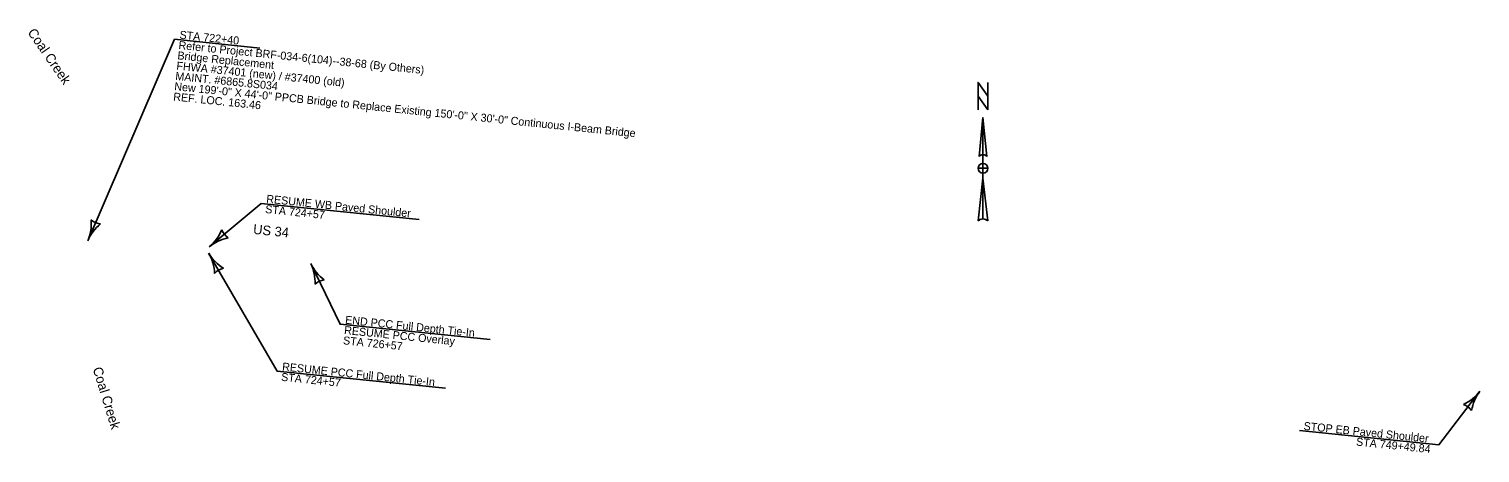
# Model space of a CAD drawing. Extents: x 22712865 to 22760106, y 6235088 to 6238602.
# Drawn here: x 22749200 to 22752029, y 6237597 to 6238424 of the extents above; entities that cross this region are included whole.
import ezdxf

# ---------------------------------------------------------------- set-up
doc = ezdxf.new("R2010")
doc.units = 0
for name, color, linetype in [('Default', 7, 'Continuous'), ('Draft_3', 7, 'Continuous'), ('dsnTextOdd', 7, 'Continuous')]:
    doc.layers.add(name, color=color, linetype=linetype)

msp = doc.modelspace()

# ---------------------------------------------------------------- linework, layer by layer
at = {"layer": 'Draft_3'}
for points in [[(22749314.9, 6238011), (22749484.1, 6238403.8), (22749650.6, 6238386.7)], [(22749551.8, 6237998.9), (22749653.1, 6238083.9), (22749960.8, 6238052.5)], [(22749550.6, 6237986.9), (22749684, 6237756.9), (22750012.5, 6237723.4)], [(22749749.6, 6237966.6), (22749806.8, 6237848.1), (22750099.4, 6237818.2)], [(22752028.8, 6237717.7), (22751948.8, 6237613.2), (22751677.3, 6237641)]]:
    msp.add_lwpolyline(points, dxfattribs=at)
for centre, radius, start, end in [((22749236.8, 6238044.6), 85, 336.7001, 4.7726), ((22749393, 6237977.4), 85, 128.6276, 156.7001), ((22749343.1, 6238076.5), 32.8, 228.9668, 264.4335), ((22749497.2, 6238064), 85, 310.0417, 338.1142), ((22749606.5, 6237933.8), 85, 101.9692, 130.0417), ((22749606.4, 6238044.7), 32.8, 202.3084, 237.7751), ((22749624.2, 6238029.6), 85, 210.1118, 238.1843), ((22749477.1, 6237944.3), 85, 2.0393, 30.1118), ((22749586.4, 6237925.3), 32.8, 102.3784, 137.8451), ((22749826.1, 6238003.6), 85, 205.7773, 233.8498), ((22749673, 6237929.6), 85, 357.7049, 25.7773), ((22749780.6, 6237902.4), 32.8, 98.044, 133.5107), ((22751961.3, 6237769.4), 85, 294.4854, 322.5578), ((22752096.3, 6237666), 85, 142.5578, 170.6303), ((22751985.5, 6237661.1), 32.8, 34.8245, 70.2912)]:
    msp.add_arc(centre, radius, start, end, dxfattribs=at)
at = {"layer": 'dsnTextOdd'}
for p, q in [((22751060, 6238251.2), (22751067.6, 6238175.2)), ((22751060, 6238251.2), (22751060, 6238053.5)), ((22751052.6, 6238175.9), (22751054.1, 6238177.5)), ((22751052.3, 6238175.2), (22751052.3, 6238175.2)), ((22751050.4, 6238049.7), (22751060, 6238133.3)), ((22751060, 6238142.8), (22751060, 6238142.8))]:
    msp.add_line(p, q, dxfattribs=at)
msp.add_lwpolyline([(22751069.5, 6238266.4), (22751050.4, 6238293.1), (22751050.4, 6238319.7), (22751069.5, 6238293.1)], close=True, dxfattribs=at)
for points in [[(22751050.4, 6238266.4), (22751050.4, 6238319.7), (22751069.5, 6238293.1), (22751069.5, 6238319.7)], [(22751052.3, 6238175.2), (22751060, 6238251.2), (22751060, 6238179)], [(22751060, 6238142.8), (22751060, 6238152.4), (22751050.4, 6238152.4)], [(22751069.5, 6238152.4), (22751060, 6238152.4), (22751060, 6238161.9)], [(22751060, 6238053.5), (22751060, 6238133.3), (22751069.5, 6238049.7)]]:
    msp.add_lwpolyline(points, dxfattribs=at)
for centre, radius, start, end in [((22751060, 6238169.5), 9.51, 90.0204, 143.1257), ((22751060, 6238169.5), 9.5, 36.8481, 90.0218), ((22751060, 6238152.4), 9.51, 90, 180), ((22751060, 6238152.4), 9.51, 180, 270), ((22751060, 6238152.4), 9.51, 0, 90), ((22751060, 6238152.4), 9.51, 270, 360), ((22751059.9, 6238039.7), 13.8, 89.9894, 133.619), ((22751060, 6238039.7), 13.8, 46.4021, 90.0006)]:
    msp.add_arc(centre, radius, start, end, dxfattribs=at)

# ---------------------------------------------------------------- texts
at = {"layer": 'Default'}
for s, rotation, p in [('Coal Creek', 304.618, (22749196.8, 6238417)), ('US 34', 354.171, (22749636.7, 6238024.5)), ('Coal Creek', 287.0563, (22749324.4, 6237761.6))]:
    msp.add_text(s, height=18.75, rotation=rotation, dxfattribs=at).set_placement(p)
at = {"layer": 'Draft_3'}
for s, height, rotation, p in [('STA 722+40', 15.6, 354.1689, (22749493.3, 6238405.1)), ('Bridge Replacement', 15.601, 354.1689, (22749489.2, 6238364.9)), ('Refer to Project BRF-034-6(104)--38-68 (By Others)', 15.601, 354.1689, (22749491.3, 6238385)), ('FHWA #37401 (new) / #37400 (old)', 15.601, 354.1689, (22749487.2, 6238344.8)), ('New 199\'-0" X 44\'-0" PPCB Bridge to Replace Existing 150\'-0" X 30\'-0" Continuous I-Beam Bridge', 15.601, 354.1689, (22749483.1, 6238304.7)), ('MAINT. #6865.8S034', 15.601, 354.1689, (22749485.1, 6238324.8)), ('REF. LOC. 163.46', 15.601, 354.1689, (22749481, 6238284.6)), ('RESUME WB Paved Shoulder', 15.601, 354.1689, (22749662.4, 6238085.3)), ('STA 724+57', 15.6, 354.1689, (22749660.3, 6238065.2)), ('RESUME PCC Overlay', 15.601, 354.1689, (22749814.1, 6237829.3)), ('END PCC Full Depth Tie-In', 15.601, 354.1689, (22749816.1, 6237849.4)), ('STA 726+57', 15.6, 354.1689, (22749812, 6237809.3)), ('STA 724+57', 15.6, 354.1689, (22749691.3, 6237738.1)), ('RESUME PCC Full Depth Tie-In', 15.601, 354.1689, (22749693.3, 6237758.2)), ('STOP EB Paved Shoulder', 15.601, 354.1663, (22751684.4, 6237642.5)), ('STA 749+49.84', 15.601, 354.1663, (22751786.7, 6237611.8))]:
    msp.add_text(s, height=height, rotation=rotation, dxfattribs=at).set_placement(p)

doc.saveas('drawing.dxf')
